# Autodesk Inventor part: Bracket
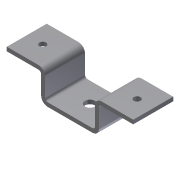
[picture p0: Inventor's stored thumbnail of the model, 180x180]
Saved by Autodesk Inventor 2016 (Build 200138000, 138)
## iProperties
Shininess: 64.0
Length Units: 11269
Angle Units: 11279
Time Units: 11290
Mass Units: 11283
Length Display Precision: 3
Angle Display Precision: 2
Compacted: True
Part Number: Bracket
Document SubType Name: Modeling
Created: 2003-01
Designer: Owner
Density: 1 g/cm^3
Material: Generic
Appearance: Default
Density: 0.0
Volumn: 0.0
Area: 0.0
PropertySet Name: Model Information
Control State: 0
Master: False
Checked Out: False
Author: Owner
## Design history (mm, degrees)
node "Sketch1"
sketch "Sketch2"
  geometry: L1 (487.39, 112.858)-(199.89, 112.858); L2 (199.89, 112.858)-(199.89, -95.142); L3 (199.89, -95.142)-(-175.11, -95.142); L4 (-175.11, -95.142)-(-175.11, 112.858); L5 (-175.11, 112.858)-(-462.61, 112.858); L6 (-462.61, 82.858)-(-205.11, 82.858); L7 (-205.11, 82.858)-(-205.11, -125.142); L8 (-205.11, -125.142)-(229.89, -125.142); L9 (229.89, -125.142)-(229.89, 82.858); L10 (229.89, 82.858)-(487.39, 82.858); L11 (487.39, 112.858)-(487.39, 82.858); L12 (-462.61, 112.858)-(-462.61, 82.858)
  constraints: 24 end point, 5 parallel, 3 perpendicular, 2 collinear, 2 equal length, 1 horizontal, 4 other
  dimensions: "d0" = 375 distance between parallel lines of L4 L2; "d1" = 950 distance of L5.end L1.start; "d2" = 30 distance between parallel lines of L1 L10; "d3" = 238 distance between parallel lines of L5 L8
extrude "Extrusion1" new body sketch "Sketch2" stored distance "d4" = 300; taper "d5" = 0 deg
fillet "Fillet1" dims "d6" = 20
fillet "Fillet2" dims "d7" = 50
sketch "Sketch3"
  geometry: L1 (237.5, 300)-(0, 300) reference; L2 (0, 300)-(0, 0) reference; 1 further point
  dimensions: "d8" = 120 distance from line of L2 point (120, 150); "d9" = 150 distance from line of L1 point (120, 150)
hole "Hole1" sketch "Sketch3" at (120, 150) diameter "d10" = 50; stored, may be unused: countersink angle "d14" = 82 deg, drill point angle "d16" = 118 deg; dims "d11" = 6, "d12" = 4, "d13" = 2, "d15" = 8
pattern_linear "Rectangular Pattern1" dims "d19" = 710
sketch "Sketch4"
  geometry: L1 (0, -300)-(335, -300) reference; 1 further point
  dimensions: "d20" = 150 distance from line of L1 point (167.5, -150)
hole "Hole2" sketch "Sketch4" at (167.5, -150) diameter "d21" = 75; stored, may be unused: countersink angle "d25" = 82 deg, drill point angle "d27" = 118 deg; dims "d22" = 6, "d23" = 4, "d24" = 2, "d26" = 8
body "Solid1"
